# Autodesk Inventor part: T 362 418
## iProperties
Created: 2005-12
Part Number: T 362 418
Material: Durethan BKV 30 H
Document SubType Name: Modeling
Designer: I.Baliuc
Manufacturer: Standard
Standards Organization: Custom
Description: Halteteil
Density: 0.94 g/cm^3
Title: Halteteil
Company: Mayer & Müller AG Schaltgeräte
Author: T.Messerschmitt
Keywords: 213549
Revision Number: 362418
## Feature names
1. Extrusion2
2. Bohrung1 [Hole]
3. Bohrung2 [Hole]
